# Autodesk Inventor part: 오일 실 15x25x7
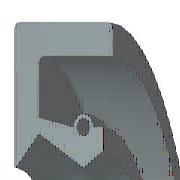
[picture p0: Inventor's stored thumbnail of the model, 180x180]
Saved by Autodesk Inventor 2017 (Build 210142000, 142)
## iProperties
Created: 2012-02
Part Number: 오일 실 15x25x7
Material: 고무
Description: 오일-실
Document SubType Name: Modeling
Standard: KS B 2804
Designer: mduedu
Standards Organization: KS
Language: ko-KR
Size Designation: D - 15 25 7
Categories: <MemberInstance><Categories><Category DisplayName="샤프트 부품" InternalName="7f7aeb1f-a693-4053-b835-cee3144e0d98" Mnemonic="SHFT"><Category DisplayName="실링" Intern
Density: 0.93 g/cm^3
Appearance: 고무 - 검은색 - 버전 1.1
IsCustomPart: 1
Author: mduedu
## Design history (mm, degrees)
revolve "본체" stored, may be unused: angle "d17" = 90 deg
revolve "스프링1" stored, may be unused: angle "d18" = 90 deg
body "Solid1"
sketch "스케치1"
  geometry: L1 (0, 12.5)-(7, 12.5); L2 (7, 10.75)-(1.75, 10.75); L3 (1.75, 9.25)-(4.9, 7.5); L4 (4.9, 7.5)-(0, 7.5); L5 (0, 0)-(9.586, 0) reference; L6 (4.9, 7.5)-(6.3, 8.375); L7 (0, 18)-(0, -3) reference; L8 (-1.941, 0)-(11.507, 0) reference; L9 (4.2, 9.6)-(1.75, 10.09); L10 (1.75, 10.09)-(1.75, 10.75); L11 (0, 12.5)-(0, 7.588); L12 (4.9, 7.5)-(0, 7.5); L13 (1.75, 9.25)-(0.152, 7.528); L14 (7, 12.5)-(7, 10.75); L15 (5.6, 9.6)-(6.3, 9.6); L16 (6.3, 9.6)-(6.3, 8.375); C1 r 0.455 at (4.9, 9.6); A1 r 0.7 centre (4.9, 9.6) between (5.6, 9.6) and (4.2, 9.6); A2 r 0.088 centre (0.088, 7.588) between (0, 7.588) and (0.152, 7.528); 1 further point
  constraints: 28 end point, 5 horizontal alignment, 5 point on line, 4 point on circle, 4 vertical alignment, 3 centre point, 3 tangent, 2 collinear, 2 horizontal, 2 perpendicular, 1 coincident, 1 parallel
  dimensions: "d0" = 25 diameter of L1 L5 (= SD2); "d1" = 1.75 distance of L1.end L2.start (= SD); "d2" = 0.91 diameter of C1 (= SPDI); "d3" = 1.4 diameter of A1 (= SPDA); "d4" = 15 diameter of L3.end L5 (= NND); "d5" = 18.5 diameter of L3.start L5 (= TKDM); "d7" = 20.18 diameter of L9.end L5 (= TKDM + 0.24 x SWDT); "d8" = 1.75 distance between parallel lines of L11 L10 (= SD); "d9" = 4.9 distance from line of L11 C1.centre (= SPDST); "d10" = 19.2 diameter of C1.centre L5 (= HLDM); "d11" = 0.0875 radius of A2 (= 0.25 x LAB); "d12" = 6.3 distance between parallel lines of L11 L16 (= SDI); "d13" = 16.75 diameter of L6.end L5 (= ABDM); "d14" = 7 distance from line of L11 L1.end (= SWDT)
fillet "모깎기1" dims "d6" = 0.3 (= RR)
other parameters: "SD2" = 25 [user parameter; used in 1 equation term], "SWDT" = 7 [user parameter; used in 2 equation terms], "RR" = 0.3 [user parameter; used in 1 equation term], "SD" = 1.75 [user parameter; used in 2 equation terms], "NND" = 15 [user parameter; used in 1 equation term], "SPDA" = 1.4 [user parameter; used in 1 equation term], "SPDI" = 0.91 [user parameter; used in 1 equation term], "TKDM" = 18.5 [user parameter; used in 2 equation terms], "HLDM" = 19.2 [user parameter; used in 1 equation term], "ABDM" = 16.75 [user parameter; used in 1 equation term], "SDI" = 6.3 [user parameter; used in 1 equation term], "SPDST" = 4.9 [user parameter; used in 1 equation term], "LAB" = 0.35 [user parameter; used in 1 equation term], "d15" = 0, "d16" = 0, "d19" = 0
